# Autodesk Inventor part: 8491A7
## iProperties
Shininess: 74.0
Length Units: 11272
Angle Units: 11279
Time Units: 11290
Mass Units: 11286
Length Display Precision: 3
Angle Display Precision: 2
Compacted: True
Created: 2001-08
Part Number: 8491A7
Cost Center: MCMASTER
Material: Purchased
Description: 1 ID 1.25 OD 1" L DRILL BUSHING
Vendor: MCMASTER
Document SubType Name: Modeling
Designer: MG
Density: 2.71
Volumn: 4.021990615336392
Area: 28.502295699234246
PropertySet Name: Model Information
Control State: 0
Master: False
Checked Out: False
Author: Administrator
